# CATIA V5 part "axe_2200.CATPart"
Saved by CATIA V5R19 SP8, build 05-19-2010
Part number: axe_2200
Bounding box of the stored display mesh (mm): x -260 to 260, y -259.809 to 259.809, z 0 to 2200
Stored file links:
  M:\EU_thinkMotion\IAO_2010\iao\IAO_MMS_Groupe1\Problemes\gduval\Gduval\train d'aterrissage squelette + piece kinematic\axe_2200.CATPart
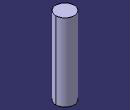
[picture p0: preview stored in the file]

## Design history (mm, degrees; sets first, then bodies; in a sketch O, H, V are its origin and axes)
Body1 (main body)
  Sketch1 on xy-plane, origin (0, 0, 0), H (1, 0, 0), V (0, 1, 0)
    circle A1 centre (0, 0) radius 260
    point P1 (0, 260)
    radius A1 = 260
    coincidence: A1 P1, P1 V
  Pad1: profile Sketch1, direction (0, 0, 1), length 2200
